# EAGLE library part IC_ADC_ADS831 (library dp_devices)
8-bit 80MHz ADC
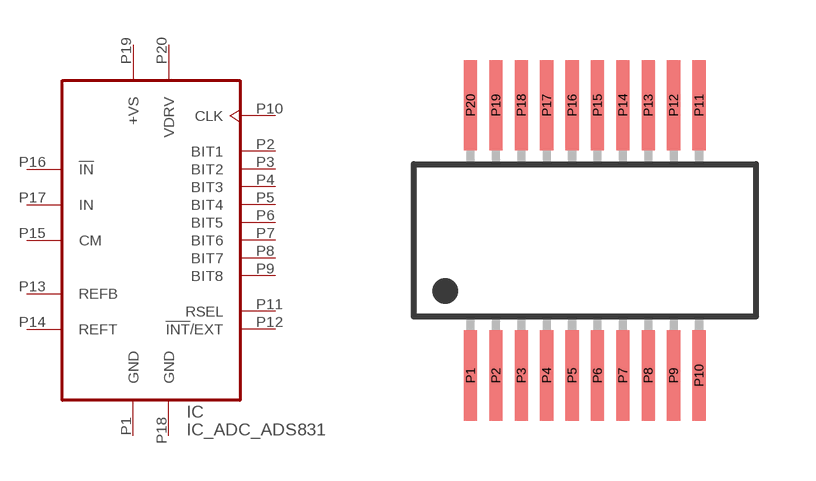
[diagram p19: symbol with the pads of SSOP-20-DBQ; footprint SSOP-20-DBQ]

Designator prefix IC

## IC_ADC_ADS831  [SSOP-20-DBQ]
P1  GND  sup
P2  BIT1
P3  BIT2
P4  BIT3
P5  BIT4
P6  BIT5
P7  BIT6
P8  BIT7
P9  BIT8
P10  CLK  in
P11  RSEL
P12  !INT!/EXT
P13  REFB
P14  REFT
P15  CM
P16  !IN
P17  IN
P18  GND  sup
P19  +VS  sup
P20  VDRV  pwr

## Footprint SSOP-20-DBQ (pad centres in mm)
SSOP20-DBQ package 0.025 inch pitch
smd 0.33 x 2.261: P1 -2.857,-3.378; P2 -2.223,-3.378; P3 -1.587,-3.378; P4 -0.953,-3.378; P5 -0.318,-3.378; P6 0.318,-3.378; P7 0.953,-3.378; P8 1.587,-3.378; P9 2.223,-3.378; P10 2.857,-3.378; P11 2.857,3.378; P12 2.223,3.378; P13 1.587,3.378; P14 0.953,3.378; P15 0.318,3.378; P16 -0.318,3.378; P17 -0.953,3.378; P18 -1.587,3.378; P19 -2.223,3.378; P20 -2.857,3.378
